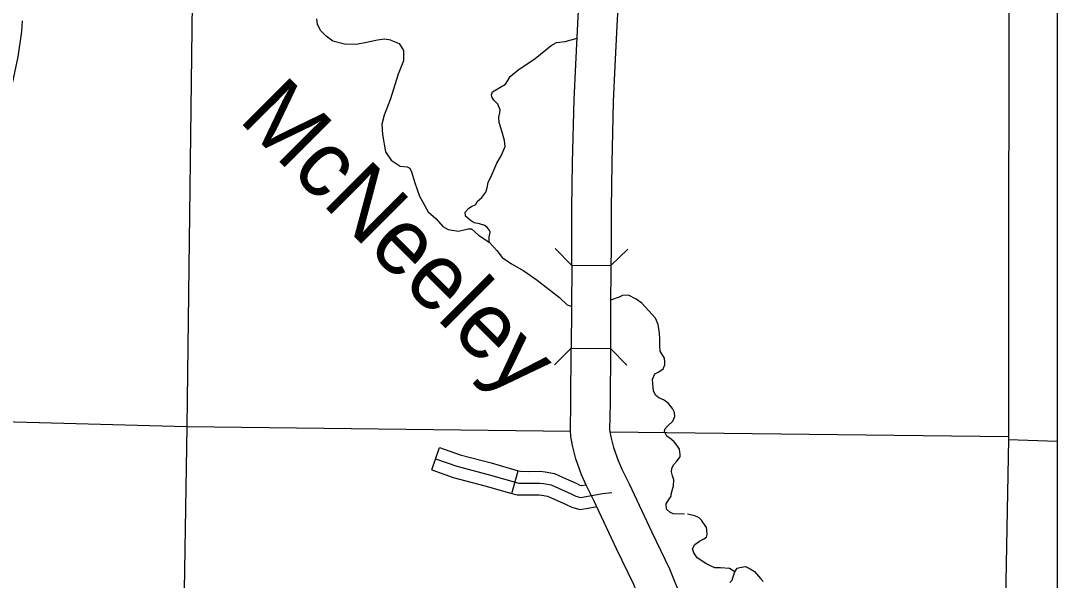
# Model space of a CAD drawing. Extents: x 8749 to 11879, y 13275 to 15339.
# Drawn here: x 10827.5 to 10959.7, y 13729.3 to 13800.6 of the extents above; entities that cross this region are included whole.
import ezdxf

# ---------------------------------------------------------------- set-up
doc = ezdxf.new("R2010")
doc.units = 0
for name, color, linetype in [('Level 10', 7, 'Continuous'), ('Level 31', 7, 'Continuous'), ('Level 32', 7, 'Continuous'), ('Level 35', 7, 'Continuous'), ('Level 37', 7, 'Continuous'), ('Level 4', 7, 'Continuous'), ('Level 40', 7, 'Continuous'), ('Level 5', 7, 'Continuous'), ('R_Draft', 7, 'Continuous')]:
    doc.layers.add(name, color=color, linetype=linetype)

msp = doc.modelspace()

# ---------------------------------------------------------------- linework, layer by layer
at = {"layer": 'Level 10'}
msp.add_line((10897.71, 13758.83), (10902.71, 13758.8), dxfattribs=at)
for points in [[(10904.22, 13810.47), (10903.86, 13804.97), (10903.58, 13800.79), (10903.29, 13794.78), (10903.08, 13790.3), (10902.9, 13782.42), (10902.8, 13776.62)], [(10897.8, 13776.71), (10897.9, 13782.52), (10898.09, 13790.48), (10898.3, 13795.02), (10898.59, 13801.08), (10898.87, 13805.3), (10898.96, 13806.6)], [(10897.78, 13769.4), (10897.8, 13771.36), (10897.8, 13776.67)], [(10902.8, 13776.67), (10902.8, 13771.34), (10902.78, 13769.36)], [(10897.78, 13769.4), (10897.75, 13764), (10897.71, 13758.83)], [(10902.78, 13769.36), (10897.78, 13769.4)], [(10902.78, 13769.36), (10902.75, 13763.97), (10902.71, 13758.8)], [(10908.25, 13720.55), (10907.59, 13723.1), (10906.9, 13725.65), (10905.69, 13728.7), (10903.5, 13733.26), (10900.64, 13739.36), (10899.65, 13741.3), (10899.04, 13742.7), (10898.32, 13744.72), (10897.88, 13746.44), (10897.65, 13747.6), (10897.61, 13748.35), (10897.67, 13751.9), (10897.71, 13758.83)], [(10902.71, 13758.8), (10902.67, 13751.85), (10902.62, 13748.44), (10902.63, 13748.22), (10902.76, 13747.55), (10903.11, 13746.18), (10903.69, 13744.54), (10904.18, 13743.43), (10905.13, 13741.56), (10908.01, 13735.4), (10910.27, 13730.71), (10911.66, 13727.23), (10912.42, 13724.37), (10913.1, 13721.75)]]:
    msp.add_lwpolyline(points, dxfattribs=at)
at = {"layer": 'Level 31'}
msp.add_lwpolyline([(10825.91, 13789.96), (10826.03, 13790.59), (10827.19, 13795.96), (10827.66, 13799.21), (10827.71, 13800.58)], dxfattribs=at)
at = {"layer": 'Level 32'}
for p, q in [((10879.92, 13743.35), (10880.92, 13746.17)), ((10890.14, 13740.34), (10890.96, 13743.23))]:
    msp.add_line(p, q, dxfattribs=at)
for points in [[(10880.92, 13746.17), (10883.55, 13745.24), (10887.5, 13744.21), (10890.96, 13743.23)], [(10880.42, 13744.76), (10883.11, 13743.81), (10887.11, 13742.76), (10891.04, 13741.65), (10892.26, 13741.63), (10893.7, 13741.65), (10894.19, 13741.61), (10895.15, 13741.43), (10896.08, 13741), (10897.7, 13740.27), (10898.32, 13739.98), (10898.92, 13739.83), (10899.63, 13739.92), (10901.72, 13740.32), (10902.88, 13740.46)], [(10879.92, 13743.35), (10882.67, 13742.37), (10886.71, 13741.31), (10890.14, 13740.34)], [(10890.96, 13743.23), (10891.26, 13743.15), (10892.26, 13743.13), (10893.76, 13743.15), (10894.4, 13743.09), (10895.6, 13742.87), (10896.7, 13742.37), (10898.33, 13741.63), (10898.83, 13741.4), (10899.02, 13741.35), (10899.6, 13741.42)], [(10890.14, 13740.34), (10890.82, 13740.15), (10892.26, 13740.13), (10893.65, 13740.15), (10893.99, 13740.12), (10894.69, 13739.99), (10895.46, 13739.64), (10897.07, 13738.91), (10897.81, 13738.56), (10898.82, 13738.3), (10899.87, 13738.43), (10900.97, 13738.65)]]:
    msp.add_lwpolyline(points, dxfattribs=at)
at = {"layer": 'Level 35'}
for points in [[(10874.72, 13798.12), (10873.89, 13798.22), (10873, 13798.09), (10871.59, 13797.79), (10870.28, 13797.54), (10868.78, 13797.59), (10867.29, 13797.97), (10866.46, 13798.63), (10865.8, 13799.31), (10865.35, 13800.09), (10865.27, 13800.83)], [(10874.72, 13798.12), (10875.78, 13797.68), (10876.31, 13796.8), (10876.34, 13795.48), (10875.66, 13793.79), (10874.67, 13790.63), (10873.84, 13788.55), (10873.58, 13787.39), (10873.66, 13786.08), (10874.01, 13783.85), (10874.75, 13782.79), (10875.91, 13782.06)], [(10887.85, 13790.46), (10887.59, 13790.9), (10887.57, 13791.12), (10887.69, 13791.5), (10888.63, 13792.08), (10889.34, 13792.49), (10889.64, 13792.97), (10889.92, 13793.47), (10890.9, 13794.28), (10893.12, 13795.77), (10895.17, 13797.44), (10895.85, 13797.8), (10896.96, 13797.95), (10898.46, 13798.36)], [(10888.78, 13783.34), (10889.31, 13784.54), (10889.19, 13785.3), (10889.01, 13786.06), (10888.78, 13786.79), (10888.53, 13787.62), (10888.48, 13788.28), (10888.61, 13788.86), (10888.66, 13789.24), (10888.35, 13789.95), (10887.85, 13790.46)], [(10887.27, 13772.35), (10887.24, 13772.98), (10887.39, 13773.63), (10887.27, 13773.94), (10887.06, 13774.19), (10886.71, 13774.47), (10886, 13774.7), (10885.35, 13774.82), (10884.82, 13775.15), (10884.24, 13775.66), (10884.19, 13776.16), (10884.66, 13776.69), (10884.99, 13776.92), (10885.55, 13777.17), (10885.73, 13777.55), (10886.31, 13778.06), (10886.84, 13778.72), (10886.99, 13779.3), (10887.14, 13779.96), (10887.59, 13780.94), (10888.25, 13782.41), (10888.78, 13783.34)], [(10875.91, 13782.06), (10876.79, 13781.98), (10877.15, 13781.8), (10877.35, 13781.32), (10877.75, 13779.9), (10878.36, 13778.21), (10879.49, 13776.21), (10880.48, 13775.35), (10881.34, 13774.37), (10882.02, 13773.96), (10883.33, 13773.76), (10884.57, 13774.04), (10884.98, 13774.04), (10885.88, 13773.23), (10887.27, 13772.35), (10888.21, 13771.31), (10888.92, 13770.4), (10890.08, 13769.61), (10891.67, 13768.7), (10893.39, 13767.52), (10896.24, 13765.32)], [(10908.97, 13760.77), (10908.82, 13761.87), (10908.47, 13762.65), (10906.73, 13764.6), (10905.99, 13765.08), (10905.03, 13765.59), (10904.25, 13765.56), (10903.85, 13765.33)], [(10897.75, 13764.17), (10897.24, 13764.32), (10896.24, 13765.32)], [(10903.85, 13765.33), (10902.75, 13764.96)], [(10909.51, 13752.28), (10908.9, 13752.5), (10908.49, 13752.86), (10908.22, 13753.41), (10908.12, 13754.32), (10908.07, 13754.9), (10908.37, 13755.56), (10908.9, 13755.81), (10909.45, 13756.22), (10909.66, 13756.7), (10909.68, 13757.1), (10909.61, 13757.58), (10909.08, 13758.47), (10909.03, 13759.23), (10909.03, 13760.01), (10908.97, 13760.77)], [(10909.91, 13747.64), (10909.63, 13748.21), (10909.66, 13748.51), (10910.01, 13748.92), (10910.69, 13749.53), (10910.94, 13750.13), (10910.89, 13750.64), (10910.64, 13751.17), (10910.14, 13751.78), (10909.76, 13752.1), (10909.51, 13752.28)], [(10912.18, 13737.68), (10910.72, 13737.73), (10910.31, 13737.93), (10909.88, 13738.31), (10909.81, 13738.99), (10910.16, 13739.57), (10910.46, 13740), (10910.46, 13740.23), (10910.77, 13741.29), (10910.82, 13742.05), (10910.62, 13742.58), (10910.49, 13743.09), (10910.57, 13743.54), (10910.79, 13744.02), (10911.2, 13744.45), (10911.6, 13744.98), (10911.6, 13745.31), (10911.53, 13745.99), (10911.2, 13746.47), (10910.87, 13746.9), (10910.49, 13747.21), (10909.91, 13747.64)], [(10918.58, 13730.34), (10917.92, 13730.76), (10916.78, 13730.84), (10916.02, 13730.84), (10915.57, 13731.04), (10914.91, 13731.4), (10913.77, 13732.13), (10913.37, 13732.74), (10913.19, 13733.27), (10913.47, 13733.82), (10914.1, 13734.25), (10914.63, 13734.53), (10914.99, 13734.76), (10915.06, 13735.09), (10915.01, 13735.67), (10914.99, 13735.97), (10914.33, 13736.91), (10914.03, 13737.21), (10913.47, 13737.49), (10912.56, 13737.67)], [(10917.95, 13728.97), (10918.25, 13729.27), (10918.33, 13729.55), (10918.58, 13730.34), (10918.88, 13730.79), (10919.21, 13730.89), (10919.97, 13731.02), (10920.55, 13730.72), (10921.11, 13730.36), (10921.86, 13729.5), (10922.19, 13729.1)]]:
    msp.add_lwpolyline(points, dxfattribs=at)
at = {"layer": 'Level 37'}
for points in [[(10897.78, 13769.4), (10895.68, 13771.54)], [(10904.92, 13771.47), (10902.78, 13769.37)], [(10895.58, 13756.73), (10897.71, 13758.83)], [(10902.71, 13758.8), (10904.82, 13756.67)]]:
    msp.add_lwpolyline(points, dxfattribs=at)
at = {"layer": 'Level 4'}
msp.add_lwpolyline([(10953.53, 13820.42), (10953.48, 13747.58), (10953.48, 13747.19), (10951.54, 13643.03), (10951.54, 13642.23), (10951.1, 13546.98)], dxfattribs=at)
at = {"layer": 'Level 5'}
for points in [[(10849.48, 13813.07), (10848.7, 13748.87)], [(10823.5, 13749.53), (10848.7, 13748.87)], [(10848.7, 13748.87), (10846.99, 13644.47)], [(10848.7, 13748.87), (10897.61, 13748.27)], [(10902.63, 13748.2), (10953.48, 13747.58)], [(10953.48, 13747.19), (10959.72, 13746.99)]]:
    msp.add_lwpolyline(points, dxfattribs=at)
at = {"layer": 'R_Draft'}
msp.add_lwpolyline([(9678.09, 14456.3), (10959.72, 14456.3), (10959.72, 13439.87), (9678.09, 13439.87)], close=True, dxfattribs=at)

# ---------------------------------------------------------------- texts
at = {"layer": 'Level 35'}
msp.add_text('McNeeley', height=8.448, rotation=314.9717, dxfattribs=at).set_placement((10855.17, 13787.93))
at = {"layer": 'Level 40'}
msp.add_text('UNION PACIFIC RR.', height=8.448, rotation=21.3423, dxfattribs=at).set_placement((10739.39, 13784.33))

doc.saveas('drawing.dxf')
